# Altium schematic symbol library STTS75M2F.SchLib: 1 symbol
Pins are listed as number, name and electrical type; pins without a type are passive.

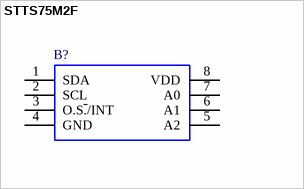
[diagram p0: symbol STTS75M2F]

## STTS75M2F
designator B?
STTS75M2F, 12bit Temperature Sensor +/-3C Serial-I2C 2.7 to 5.5V 8-Pin SOIC; Manufacturer_Name: STMicroelectronics; Geometry.Height: 1.75mm
footprint SOIC127P600X175-8N
pins: 1 SDA, 2 SCL, 3 O.S~{.}/INT, 4 GND, 5 A2, 6 A1, 7 A0, 8 VDD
